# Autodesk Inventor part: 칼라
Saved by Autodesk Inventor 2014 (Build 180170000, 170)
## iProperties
Created: 2026-05
Part Number: 칼라
Material: 일반
Document SubType Name: Modeling
Designer: dg
Density: 1 g/cm^3
Appearance: 기본값
Author: dg
Author: jhkim
Creation Date: 2026-04-27
Sending System: Autodesk Inventor 2027
Preprocessor: ST-DEVELOPER v20.1
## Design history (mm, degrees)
node "칼라1"
node "솔리드1"
node "기준1"
